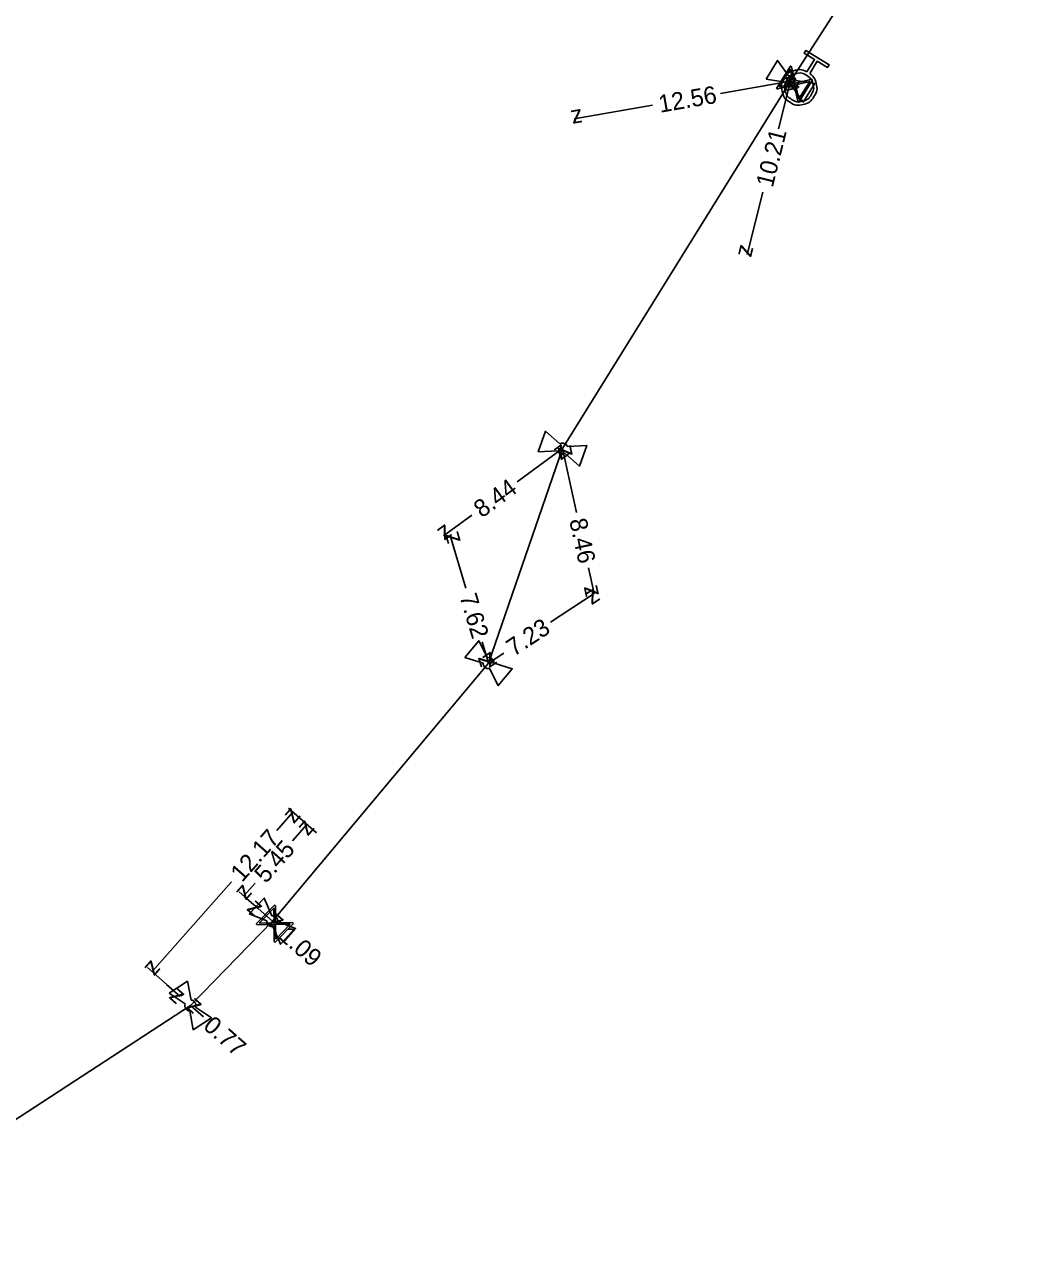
# Model space of a CAD drawing. Extents: x -638315 to -636370, y -1116147 to -1115110.
# Drawn here: x -637077.5 to -637020.5, y -1116022.5 to -1115952.2 of the extents above; entities that cross this region are included whole.
import ezdxf

# ---------------------------------------------------------------- set-up
doc = ezdxf.new("R2010")
doc.units = 0
for name, color, linetype in [('Default', 7, 'Continuous'), ('VP Hydrant', 7, 'Continuous'), ('VP Kótování', 7, 'Continuous'), ('VP Lomový bod', 7, 'Continuous'), ('VP Přípojka', 7, 'Continuous'), ('VP Čára nerozlišená', 7, 'Continuous'), ('VP Řad', 7, 'Continuous'), ('VP Šoupě', 7, 'Continuous')]:
    doc.layers.add(name, color=color, linetype=linetype)

msp = doc.modelspace()

# ---------------------------------------------------------------- linework, layer by layer
at = {"layer": 'Default'}
for points in [[(-637032.627, -1115954.992), (-637032.337, -1115955.207), (-637032.255, -1115955.563), (-637032.162, -1115955.966), (-637032.382, -1115956.319), (-637032.6, -1115956.671), (-637033.003, -1115956.765), (-637033.406, -1115956.858), (-637033.759, -1115956.639), (-637034.109, -1115956.422), (-637034.204, -1115956.019), (-637034.299, -1115955.616), (-637034.081, -1115955.265), (-637033.862, -1115954.911), (-637033.46, -1115954.816), (-637033.103, -1115954.729), (-637032.783, -1115954.895)], [(-637032.802, -1115955.097), (-637033.09, -1115954.919), (-637033.416, -1115954.996), (-637033.743, -1115955.072), (-637033.921, -1115955.359), (-637034.099, -1115955.646), (-637034.023, -1115955.973), (-637033.946, -1115956.3), (-637033.659, -1115956.478), (-637033.374, -1115956.655), (-637033.046, -1115956.579), (-637032.719, -1115956.503), (-637032.541, -1115956.216), (-637032.362, -1115955.929), (-637032.439, -1115955.602), (-637032.515, -1115955.275), (-637032.802, -1115955.097)], [(-637033.633, -1115955.738), (-637033.684, -1115955.754), (-637033.738, -1115955.752), (-637033.822, -1115955.748), (-637033.892, -1115955.705), (-637033.961, -1115955.662), (-637034.003, -1115955.586), (-637034.029, -1115955.54), (-637034.037, -1115955.487)], [(-637033.821, -1115955.14), (-637033.771, -1115955.125), (-637033.718, -1115955.126), (-637033.632, -1115955.131), (-637033.562, -1115955.174), (-637033.493, -1115955.217), (-637033.452, -1115955.291), (-637033.426, -1115955.339), (-637033.418, -1115955.391)], [(-637046.603, -1115976.71), (-637046.648, -1115976.737), (-637046.702, -1115976.746), (-637046.785, -1115976.762), (-637046.862, -1115976.735), (-637046.939, -1115976.708), (-637046.997, -1115976.643), (-637047.032, -1115976.604), (-637047.051, -1115976.555)], [(-637046.918, -1115976.168), (-637046.873, -1115976.142), (-637046.82, -1115976.132), (-637046.735, -1115976.118), (-637046.658, -1115976.144), (-637046.581, -1115976.171), (-637046.525, -1115976.234), (-637046.489, -1115976.275), (-637046.47, -1115976.324)], [(-637051.041, -1115988.39), (-637050.989, -1115988.382), (-637050.937, -1115988.391), (-637050.852, -1115988.408), (-637050.789, -1115988.461), (-637050.727, -1115988.513), (-637050.697, -1115988.592), (-637050.678, -1115988.643), (-637050.678, -1115988.696)], [(-637050.939, -1115989.008), (-637050.992, -1115989.017), (-637051.045, -1115989.007), (-637051.128, -1115988.992), (-637051.191, -1115988.94), (-637051.253, -1115988.887), (-637051.284, -1115988.806), (-637051.303, -1115988.756), (-637051.303, -1115988.703)], [(-637063.38, -1116003.137), (-637063.329, -1116003.133), (-637063.277, -1116003.146), (-637063.194, -1116003.169), (-637063.135, -1116003.226), (-637063.076, -1116003.283), (-637063.053, -1116003.364), (-637063.037, -1116003.417), (-637063.041, -1116003.469)], [(-637063.325, -1116003.762), (-637063.378, -1116003.767), (-637063.431, -1116003.753), (-637063.512, -1116003.731), (-637063.571, -1116003.674), (-637063.629, -1116003.617), (-637063.654, -1116003.534), (-637063.669, -1116003.483), (-637063.666, -1116003.431)], [(-637068.081, -1116008.58), (-637068.134, -1116008.573), (-637068.182, -1116008.548), (-637068.257, -1116008.509), (-637068.302, -1116008.441), (-637068.346, -1116008.372), (-637068.352, -1116008.286), (-637068.356, -1116008.233), (-637068.341, -1116008.182)], [(-637067.998, -1116007.959), (-637067.947, -1116007.966), (-637067.899, -1116007.99), (-637067.823, -1116008.031), (-637067.778, -1116008.1), (-637067.733, -1116008.168), (-637067.728, -1116008.252), (-637067.725, -1116008.307), (-637067.74, -1116008.358)]]:
    msp.add_open_spline(points, degree=3, dxfattribs=at)
at = {"layer": 'VP Hydrant'}
msp.add_lwpolyline([(-637032.783, -1115954.895), (-637032.35, -1115954.198), (-637032.936, -1115953.835), (-637032.839, -1115953.679), (-637031.512, -1115954.503), (-637031.609, -1115954.659), (-637032.194, -1115954.295), (-637032.627, -1115954.992)], dxfattribs=at)
at = {"layer": 'VP Kótování'}
for points in [[(-637037.727, -1115956.135), (-637033.727, -1115955.44)], [(-637034.407, -1115958.152), (-637033.727, -1115955.44)], [(-637041.61, -1115956.81), (-637046.1, -1115957.59)], [(-637035.315, -1115961.773), (-637036.21, -1115965.34)], [(-637049.359, -1115978.34), (-637046.76, -1115976.44)], [(-637045.967, -1115980.083), (-637046.76, -1115976.44)], [(-637051.948, -1115980.234), (-637053.57, -1115981.42)], [(-637052.284, -1115984.407), (-637053.19, -1115981.4)], [(-637045.278, -1115983.25), (-637044.96, -1115984.71)], [(-637047.44, -1115986.351), (-637044.96, -1115984.71)], [(-637051.358, -1115987.479), (-637050.99, -1115988.7)], [(-637050.116, -1115988.122), (-637050.99, -1115988.7)], [(-637060.822, -1115998.408), (-637062.435, -1115996.983)], [(-637063.106, -1115998.271), (-637062.173, -1115997.215)], [(-637060.822, -1115998.408), (-637061.638, -1115997.688)], [(-637062.207, -1115998.861), (-637061.375, -1115997.92)], [(-637065.694, -1116001.2), (-637070.231, -1116006.334)], [(-637064.433, -1116002.495), (-637065.249, -1116001.775)], [(-637064.332, -1116001.267), (-637064.986, -1116002.007)], [(-637064.958, -1116002.032), (-637064.171, -1116002.727)], [(-637068.88, -1116007.527), (-637070.493, -1116006.102)], [(-637069.405, -1116007.064), (-637068.618, -1116007.759)], [(-637067.298, -1116008.926), (-637068.04, -1116008.27)]]:
    msp.add_lwpolyline(points, dxfattribs=at)
at = {"layer": 'VP Lomový bod'}
for points in [[(-637035.119, -1115955.312), (-637034.459, -1115954.25), (-637033.821, -1115955.14)], [(-637034.037, -1115955.487), (-637035.119, -1115955.312)], [(-637033.418, -1115955.391), (-637032.335, -1115955.568), (-637032.994, -1115956.63), (-637033.633, -1115955.738)], [(-637048.145, -1115976.623), (-637047.738, -1115975.441), (-637046.918, -1115976.168)], [(-637047.051, -1115976.555), (-637048.145, -1115976.623)], [(-637046.47, -1115976.324), (-637045.374, -1115976.257), (-637045.782, -1115977.438), (-637046.603, -1115976.71)], [(-637052.35, -1115988.376), (-637051.547, -1115987.418), (-637051.041, -1115988.39)], [(-637051.303, -1115988.703), (-637052.35, -1115988.376)], [(-637050.678, -1115988.696), (-637049.631, -1115989.024), (-637050.434, -1115989.982), (-637050.939, -1115989.008)], [(-637064.685, -1116003.027), (-637063.813, -1116002.131), (-637063.38, -1116003.137)], [(-637063.666, -1116003.431), (-637064.685, -1116003.027)], [(-637063.041, -1116003.469), (-637062.021, -1116003.874), (-637062.892, -1116004.77), (-637063.325, -1116003.762)], [(-637069.246, -1116007.564), (-637068.198, -1116006.882), (-637067.998, -1116007.959)], [(-637068.341, -1116008.182), (-637069.246, -1116007.564)], [(-637067.74, -1116008.358), (-637066.834, -1116008.977), (-637067.881, -1116009.659), (-637068.081, -1116008.58)]]:
    msp.add_lwpolyline(points, dxfattribs=at)
at = {"layer": 'VP Přípojka'}
for points in [[(-637033.727, -1115955.44), (-637033.48, -1115955.61), (-637033.23, -1115955.79)], [(-637063.21, -1116003.59), (-637063.353, -1116003.45)]]:
    msp.add_lwpolyline(points, dxfattribs=at)
at = {"layer": 'VP Čára nerozlišená'}
for points in [[(-637064.171, -1116002.727), (-637063.353, -1116003.45)], [(-637068.46, -1116007.58), (-637068.592, -1116007.73)]]:
    msp.add_lwpolyline(points, dxfattribs=at)
at = {"layer": 'VP Řad'}
msp.add_lwpolyline([(-637090.11, -1116022.496), (-637088.015, -1116021.282), (-637068.04, -1116008.27), (-637063.353, -1116003.45), (-637050.99, -1115988.7), (-637046.76, -1115976.44), (-637033.727, -1115955.44), (-637030.28, -1115950.07), (-637025.95, -1115945.9), (-637023.92, -1115939.39), (-637022.71, -1115934.13), (-637020.86, -1115927.49), (-637020.52, -1115917.93), (-637020.76, -1115906.31), (-637020.58, -1115902.93), (-637021.02, -1115901.01)], dxfattribs=at)
at = {"layer": 'VP Šoupě'}
for points in [[(-637032.457, -1115955.362), (-637033.247, -1115956.637), (-637033.304, -1115956.602), (-637033.329, -1115956.476), (-637033.521, -1115955.659), (-637034.466, -1115955.881), (-637034.522, -1115955.846), (-637033.731, -1115954.571), (-637033.675, -1115954.606), (-637033.456, -1115955.553), (-637032.638, -1115955.36), (-637032.513, -1115955.328), (-637032.457, -1115955.362)], [(-637034.362, -1115955.766), (-637033.541, -1115955.573), (-637033.734, -1115954.754), (-637034.362, -1115955.766)], [(-637032.619, -1115955.447), (-637033.436, -1115955.638), (-637033.244, -1115956.453), (-637032.619, -1115955.447)], [(-637062.15, -1116003.575), (-637063.196, -1116004.651), (-637063.243, -1116004.605), (-637063.241, -1116004.476), (-637063.253, -1116003.636), (-637064.224, -1116003.651), (-637064.271, -1116003.605), (-637063.225, -1116002.53), (-637063.178, -1116002.576), (-637063.167, -1116003.547), (-637062.327, -1116003.534), (-637062.197, -1116003.529), (-637062.15, -1116003.575)], [(-637062.15, -1116003.575), (-637063.196, -1116004.651), (-637063.243, -1116004.605), (-637063.241, -1116004.476), (-637063.253, -1116003.636), (-637064.224, -1116003.651), (-637064.271, -1116003.605), (-637063.225, -1116002.53), (-637063.178, -1116002.576), (-637063.167, -1116003.547), (-637062.327, -1116003.534), (-637062.197, -1116003.529), (-637062.15, -1116003.575)], [(-637064.098, -1116003.561), (-637063.255, -1116003.548), (-637063.267, -1116002.707), (-637064.098, -1116003.561)], [(-637064.098, -1116003.561), (-637063.255, -1116003.548), (-637063.267, -1116002.707), (-637064.098, -1116003.561)], [(-637062.327, -1116003.623), (-637063.165, -1116003.635), (-637063.153, -1116004.472), (-637062.327, -1116003.623)], [(-637062.327, -1116003.623), (-637063.165, -1116003.635), (-637063.153, -1116004.472), (-637062.327, -1116003.623)]]:
    msp.add_lwpolyline(points, dxfattribs=at)

# ---------------------------------------------------------------- texts
at = {"layer": 'VP Kótování'}
for s, rotation, p in [('z', 9.85762, (-637034.134, -1115956.018)), ('z', 75.92017, (-637033.364, -1115956.047)), ('12.56', 9.85762, (-637041.18, -1115957.242)), ('z', 189.8576, (-637045.693, -1115957.012)), ('10.21', 75.92017, (-637034.745, -1115961.556)), ('z', 255.92021, (-637036.573, -1115964.733)), ('z', 36.17719, (-637046.868, -1115977.139)), ('z', 102.27915, (-637046.165, -1115976.822)), ('8.44', 36.17719, (-637051.371, -1115980.431)), ('z', 216.17717, (-637053.462, -1115980.721)), ('8.46', 282.27917, (-637046.381, -1115980.531)), ('z', 106.7712, (-637052.567, -1115981.734)), ('z', 282.27913, (-637045.555, -1115984.328)), ('7.62', 286.77122, (-637052.661, -1115984.887)), ('z', 33.49225, (-637045.101, -1115985.403)), ('7.23', 33.49225, (-637049.548, -1115988.345)), ('z', 286.77124, (-637051.613, -1115988.366)), ('z', 213.49229, (-637050.849, -1115988.007)), ('z', 48.53457, (-637062.129, -1115997.921)), ('z', 48.53835, (-637061.332, -1115998.625)), ('12.17', 48.53457, (-637065.087, -1116001.268)), ('5.45', 48.53835, (-637063.726, -1116001.335)), ('z', 228.53833, (-637065.03, -1116001.301)), ('z', 318.52771, (-637064.877, -1116002.771)), ('z', 138.52773, (-637062.647, -1116003.406)), ('1.09', 318.52775, (-637063.039, -1116004.395)), ('z', 228.5346, (-637070.274, -1116005.628)), ('z', 318.52066, (-637069.324, -1116007.802)), ('z', 138.52063, (-637067.334, -1116008.227)), ('0.77', 318.52065, (-637067.367, -1116009.532))]:
    msp.add_text(s, height=1, rotation=rotation, dxfattribs=at).set_placement(p)

doc.saveas('drawing.dxf')
